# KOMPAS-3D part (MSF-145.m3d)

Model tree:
1. Ось X
2. Ось Y
3. Ось Z
4. Начало координат  (labels: Операция без истории:1)

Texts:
  Линия-выноска #1
  Линия-выноска #2
  Линия-выноска #3
  Отклонения формы и база
  Марка координационной оси
  Марка/позиционное обозначение с линией-выноской
  Марка/позиционное обозначение на линии
  Марка/позиционное обозначение без линии-выноски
